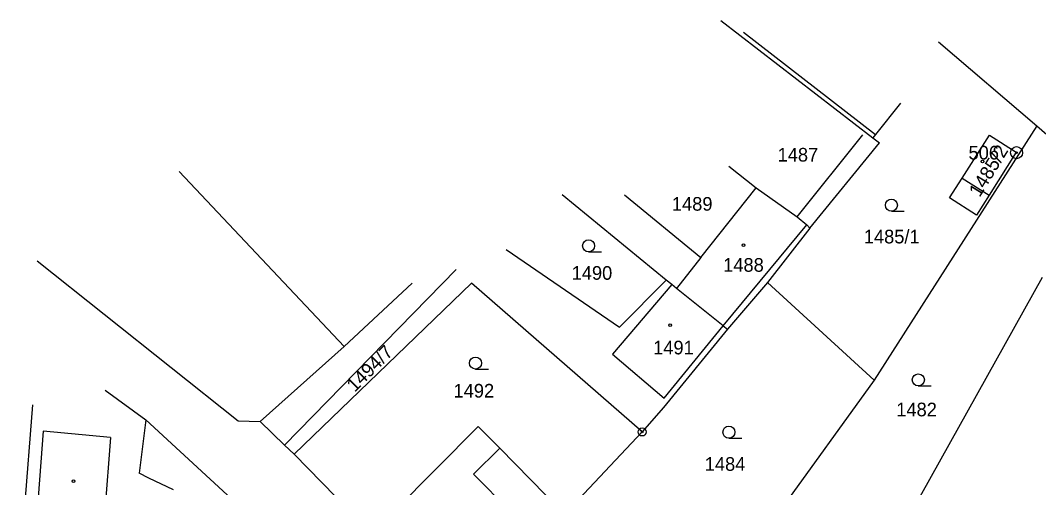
# Model space of a CAD drawing. Extents: x -763296 to -761805, y -1153670 to -1152034.
# Drawn here: x -762750.4 to -762623.5, y -1152285 to -1152226.8 of the extents above; entities that cross this region are included whole.
import ezdxf

# ---------------------------------------------------------------- set-up
doc = ezdxf.new("R2010")
doc.units = 0
for name, color, linetype in [('Vrstva 1', 7, 'Continuous'), ('Vrstva 17', 7, 'Continuous'), ('Vrstva 18', 7, 'Continuous'), ('Vrstva 19', 7, 'Continuous'), ('Vrstva 24', 7, 'Continuous'), ('Vrstva 25', 7, 'Continuous'), ('Vrstva 4', 7, 'Continuous'), ('Vrstva 6', 7, 'Continuous')]:
    doc.layers.add(name, color=color, linetype=linetype)

msp = doc.modelspace()

# ---------------------------------------------------------------- linework, layer by layer
at = {"layer": 'Vrstva 1'}
for p, q in [((-762663.13, -1152226.78), (-762644.2, -1152241.41)), ((-762636.03, -1152229.47), (-762623.75, -1152239.92)), ((-762640.76, -1152237.08), (-762643.86, -1152241)), ((-762623.75, -1152239.92), (-762644.04, -1152271.62)), ((-762623.75, -1152239.92), (-762589.87, -1152269.52)), ((-762643.86, -1152241), (-762644.2, -1152241.41)), ((-762644.2, -1152241.41), (-762643.37, -1152242.05)), ((-762633.07, -1152246.43), (-762629.66, -1152241.08)), ((-762629.66, -1152241.08), (-762626.32, -1152243.19)), ((-762652.05, -1152252.67), (-762643.37, -1152242.05)), ((-762626.32, -1152243.19), (-762629.71, -1152248.55)), ((-762662.16, -1152244.95), (-762658.75, -1152247.67)), ((-762710.08, -1152267.42), (-762730.63, -1152245.62)), ((-762634.65, -1152248.91), (-762633.07, -1152246.43)), ((-762665.61, -1152256.32), (-762658.75, -1152247.67)), ((-762658.75, -1152247.67), (-762653.63, -1152251.28)), ((-762669.96, -1152259.14), (-762682.91, -1152248.54)), ((-762675.14, -1152248.51), (-762665.61, -1152256.32)), ((-762631.3, -1152251.04), (-762634.65, -1152248.91)), ((-762629.71, -1152248.55), (-762631.3, -1152251.04)), ((-762653.63, -1152251.28), (-762652.44, -1152252.25)), ((-762652.05, -1152252.67), (-762657.32, -1152259.47)), ((-762652.44, -1152252.25), (-762652.05, -1152252.67)), ((-762689.89, -1152255.34), (-762675.78, -1152265.02)), ((-762748.3, -1152256.76), (-762723.29, -1152276.7)), ((-762675.78, -1152265.02), (-762669.96, -1152259.14)), ((-762669.25, -1152259.72), (-762669.96, -1152259.14)), ((-762655.97, -1152317.77), (-762623.06, -1152258.78)), ((-762716.31, -1152280.86), (-762694.2, -1152259.54)), ((-762701.59, -1152259.53), (-762710.08, -1152267.42)), ((-762672.94, -1152278.08), (-762694.2, -1152259.54)), ((-762668.68, -1152260.18), (-762669.25, -1152259.72)), ((-762662.84, -1152264.84), (-762668.68, -1152260.18)), ((-762657.32, -1152259.47), (-762662.31, -1152265.26)), ((-762657.32, -1152259.47), (-762644.04, -1152271.62)), ((-762662.31, -1152265.26), (-762670.26, -1152275.03)), ((-762662.84, -1152264.84), (-762662.31, -1152265.26)), ((-762720.54, -1152276.77), (-762710.08, -1152267.42)), ((-762644.04, -1152271.62), (-762664.02, -1152299.3)), ((-762739.83, -1152272.86), (-762734.79, -1152276.55)), ((-762748.9, -1152274.7), (-762750.41, -1152293.9)), ((-762670.26, -1152275.03), (-762672.94, -1152278.08)), ((-762734.79, -1152276.55), (-762735.62, -1152283.23)), ((-762734.79, -1152276.55), (-762716.98, -1152292.95)), ((-762723.29, -1152276.7), (-762720.54, -1152276.77)), ((-762720.54, -1152276.77), (-762717.49, -1152279.72)), ((-762706.61, -1152290.74), (-762693.36, -1152277.38)), ((-762693.36, -1152277.38), (-762690.66, -1152280.1)), ((-762682.55, -1152288.27), (-762672.94, -1152278.08)), ((-762717.49, -1152279.72), (-762716.31, -1152280.86)), ((-762690.66, -1152280.1), (-762682.89, -1152288.01)), ((-762706.61, -1152290.74), (-762716.31, -1152280.86)), ((-762734.39, -1152283.83), (-762735.62, -1152283.23)), ((-762731.33, -1152285.31), (-762734.39, -1152283.83))]:
    msp.add_line(p, q, dxfattribs=at)
at = {"layer": 'Vrstva 24'}
for centre, radius in [((-762626.28, -1152243.27), 0.75), ((-762626.28, -1152243.27), 0.1), ((-762672.94, -1152278.08), 0.5), ((-762672.94, -1152278.08), 0.1)]:
    msp.add_circle(centre, radius, dxfattribs=at)
at = {"layer": 'Vrstva 25'}
for p, q in [((-762641.89, -1152250.56), (-762640.29, -1152250.56)), ((-762679.61, -1152255.63), (-762678.01, -1152255.63)), ((-762693.7, -1152270.24), (-762692.1, -1152270.24)), ((-762638.53, -1152272.34), (-762636.93, -1152272.34)), ((-762662.13, -1152278.85), (-762660.53, -1152278.85))]:
    msp.add_line(p, q, dxfattribs=at)
for centre, radius in [((-762630.53, -1152244.37), 0.175), ((-762641.89, -1152249.81), 0.75), ((-762679.61, -1152254.88), 0.75), ((-762660.32, -1152254.79), 0.175), ((-762669.44, -1152264.77), 0.175), ((-762693.7, -1152269.49), 0.75), ((-762638.53, -1152271.59), 0.75), ((-762662.13, -1152278.1), 0.75), ((-762743.8, -1152284.21), 0.175)]:
    msp.add_circle(centre, radius, dxfattribs=at)
at = {"layer": 'Vrstva 4'}
for p, q in [((-762660.31, -1152228.25), (-762643.86, -1152241)), ((-762653.63, -1152251.28), (-762645.45, -1152241.05)), ((-762633.07, -1152246.43), (-762629.71, -1152248.55)), ((-762662.84, -1152264.84), (-762652.44, -1152252.25)), ((-762665.61, -1152256.32), (-762668.68, -1152260.18)), ((-762669.25, -1152259.72), (-762676.65, -1152268.4)), ((-762670.21, -1152273.85), (-762662.84, -1152264.84)), ((-762676.65, -1152268.4), (-762670.21, -1152273.85)), ((-762747.57, -1152277.99), (-762748.81, -1152294.04)), ((-762739.17, -1152278.76), (-762747.57, -1152277.99)), ((-762739.17, -1152278.76), (-762740.15, -1152291.24)), ((-762693.96, -1152283.32), (-762690.66, -1152280.1)), ((-762688.86, -1152288.47), (-762693.96, -1152283.32))]:
    msp.add_line(p, q, dxfattribs=at)
at = {"layer": 'Vrstva 6'}
msp.add_line((-762717.49, -1152279.72), (-762696.11, -1152257.85), dxfattribs=at)

# ---------------------------------------------------------------- texts
at = {"layer": 'Vrstva 17'}
msp.add_text('506', height=1.7, dxfattribs=at).set_placement((-762632.274, -1152244.12))
at = {"layer": 'Vrstva 18'}
for s, p in [('1489', (-762669.232, -1152250.5)), ('1485/1', (-762645.32, -1152254.58)), ('1490', (-762681.722, -1152259.11)), ('1492', (-762696.439, -1152273.79)), ('1482', (-762641.276, -1152276.13)), ('1484', (-762665.142, -1152282.92))]:
    msp.add_text(s, height=1.7, dxfattribs=at).set_placement(p)
msp.add_text('1494/7', height=1.7, rotation=44.97719, dxfattribs=at).set_placement((-762708.742, -1152273.199))
at = {"layer": 'Vrstva 19'}
for s, p in [('1487', (-762656.062, -1152244.38)), ('1488', (-762662.842, -1152258.11)), ('1491', (-762671.567, -1152268.41))]:
    msp.add_text(s, height=1.7, dxfattribs=at).set_placement(p)
msp.add_text('1485/2', height=1.7, rotation=58.49899, dxfattribs=at).set_placement((-762630.889, -1152248.914))

doc.saveas('drawing.dxf')
